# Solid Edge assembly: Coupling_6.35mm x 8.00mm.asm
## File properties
Author: f_grande
Template: Normal.asm
Last saved by: f_grande
Revision: 2
Application: Solid Edge
Tipo di contenuto documento: 1
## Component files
Coupling1.par
Gomma_coupling.par
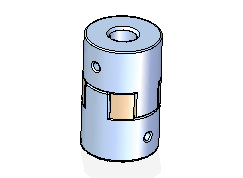
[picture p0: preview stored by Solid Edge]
